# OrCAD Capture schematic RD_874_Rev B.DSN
size B; title: DER-874 rev B; rev: B
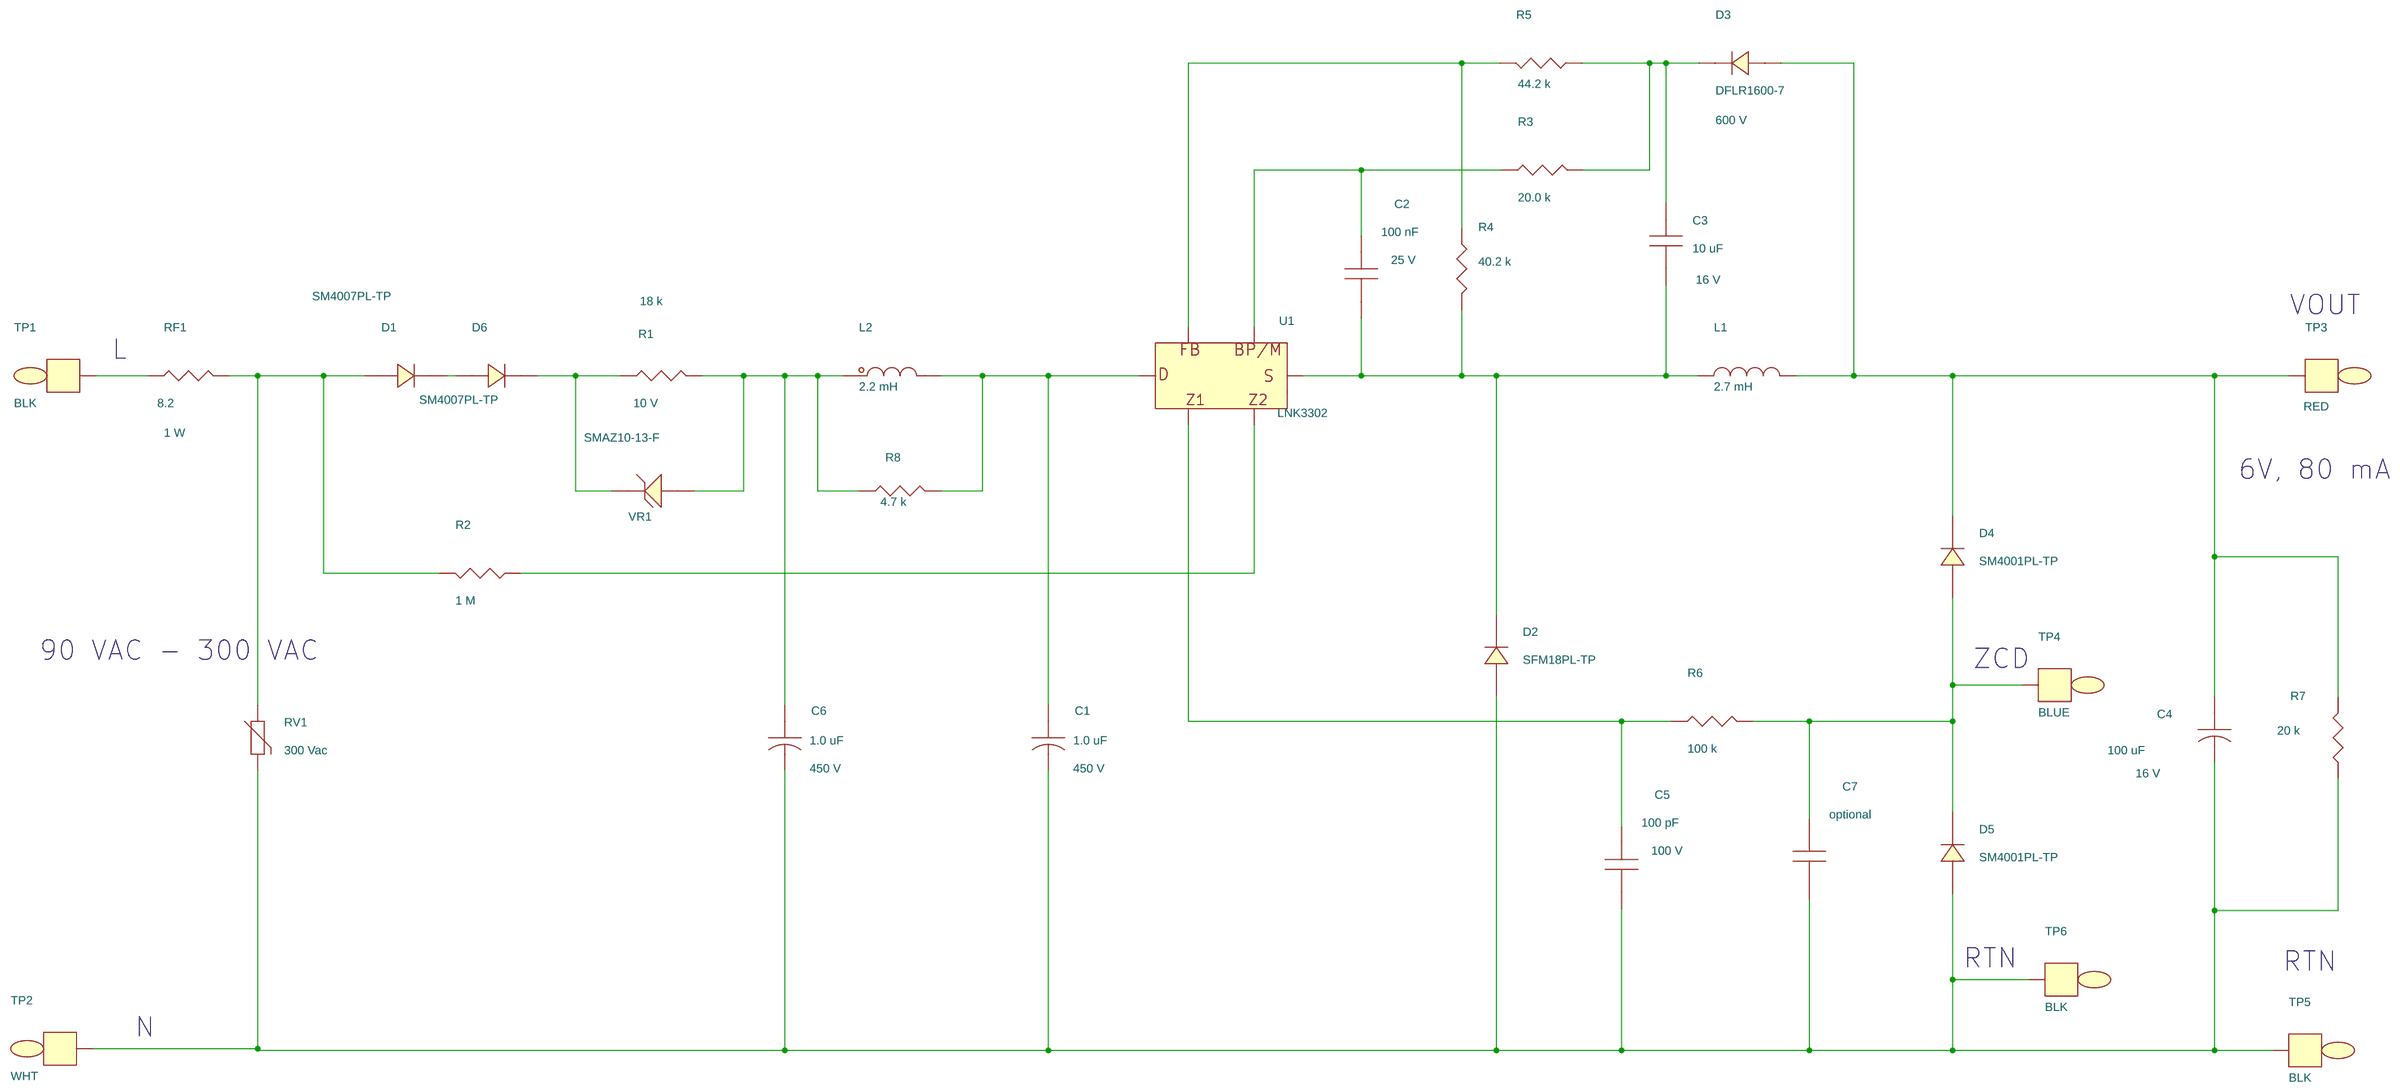
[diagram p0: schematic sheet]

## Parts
C1  1.0 uF  [pipolcapclyd320ls140030]
C2  100 nF  [pismc0805]
C3  10 uF  [pismc0805]
C4  100 uF  [pipolcapclyd248ls098028]
C5  100 pF  [pismc0805]
C6  1.0 uF  [pipolcapclyd320ls140030]
C7  optional  [pismc0805]
D1  SM4007PL-TP  [pi_sm_sod-123_12]
D2  SFM18PL-TP  [pi_sm_sod-123_12]
D3  DFLR1600-7  [pismddflr120012]
D4  SM4001PL-TP  [pi_sm_sod-123_12]
D5  SM4001PL-TP  [pi_sm_sod-123_12]
D6  SM4007PL-TP  [pi_sm_sod-123_12]
L1  2.7 mH  [pi_choke_vd8p0h7p5ls5p0d0p6]
L2  2.2 mH  [pi_choke_RL5480-1_d2]
R1  18 k  [pismr0805]
R2  1 M  [pismr0805]
R3  20.0 k  [pismr1206]
R4  40.2 k  [pismr0805]
R5  44.2 k  [pismr0805]
R6  100 k  [pismr0805]
R7  20 k  [pismr0805]
R8  4.7 k  [pismr0805]
RF1  8.2  [pi12wresd180ls575040]
RV1  300 Vac  [pi_disc276x181_ls200x83d040]
TP1  BLK  [pitpkeystone100x100]
TP2  WHT  [pitpkeystone100x100]
TP3  RED  [pitpkeystone100x100]
TP4  BLUE  [pitpkeystone100x100]
TP5  BLK  [pitpkeystone100x100]
TP6  BLK  [pitpkeystone100x100]
U1  LNK3302  [pismso8_nop3]
VR1  SMAZ10-13-F  [pismdo214ac12]

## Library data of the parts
C1 C6 = CAP_POL: ALT_SYMBOLS: pipolcapclyd320ls140030h; Disp_Voltage: 450 V; FPLIST: pipolcapclyd320ls140030,pipolcapclyd320ls140030430h,pipolcapclyd320ls140030h; Part Number: 20-00955-00; Voltage: 450 V
C2 = CAP_NP: Disp_Voltage: 25 V; Part Number: 20-08599-00; Voltage: 25 V
C3 = CAP_NP: Disp_Voltage: 16 V; Part Number: 20-08964-00; Voltage: 16 V
C4 = CAP_POL: ALT_SYMBOLS: pipolcapclyd248ls098028_h; Disp_Voltage: 16 V; FPLIST: pipolcapclyd248ls098028,pipolcapclyd248ls098028_h; Part Number: 20-09114-00; Voltage: 16V
C5 C7 = CAP_NP: Disp_Voltage: 100 V; Part Number: 20-00581-00; Voltage: 100 V
D1 D6 = DIODE: Part Number: 15-01070-00
D2 = DIODE: Part Number: 15-01634-00
D3 = DIODE: Disp_Voltage: 600 V; Part Number: 15-00826-00
D4 D5 = DIODE: Part Number: 15-01598-00; ROOM: 2
L1 = INDUCTOR: Part Number: 30-00435-00
L2 = INDUCTOR_DOT2: Part Number: 30-00272-00
R1 = R: Part Number: 05-01549-00
R2 = R: Part Number: 05-01591-00; ROOM: 1
R3 = R: Disp_Tol: 1%; Part Number: 05-00318-00
R4 = R: Disp_Tol: 1%; Part Number: 05-00742-00; Tol: 1%
R5 = R: Disp_Tol: 1%; Part Number: 05-00746-00
R6 = R: Part Number: 05-01567-00; ROOM: 1
R7 = R: Part Number: 05-01550-00; Tol: 1%
R8 = R: Part Number: 05-01535-00; ROOM: 1
RF1 = RF: ALT_SYMBOLS: pi1wvresd120ls200d040; Disp_Power: 1 W; FPLIST: pi12wresd180ls575040,pi1wvresd120ls200d040; Part Number: 05-06353-00
RV1 = VARISTOR: Part Number: 85-00037-00
TP1 TP5 TP6 = TESTPOINT: Part Number: 35-00079-00
TP2 = TESTPOINT: Part Number: 35-00081-00
TP3 = TESTPOINT: Part Number: 35-00080-00; ROOM: 2
TP4 = TESTPOINT: Part Number: 35-00397-00
U1 = LNK-TNZ: Part Number: 10-01234-00
VR1 = DIODE_ZENER: Disp_Voltage: 10 V; Part Number: 15-01323-00

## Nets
N361382: D6.1 R1.2 VR1.1
N361822: C1.2 C4.2 C5.2 C6.2 C7.2 D2.2 D5.2 R7.2 RV1.2 TP2.1 TP5.1 TP6.1
N595771: D1.2 R2.2 RF1.2 RV1.1
N596154: RF1.1 TP1.1
N596955: C2.1 R3.1 U1.7
N596963: C3.1 D3.1 R3.2 R5.1
N597007: R4.1 R5.2 U1.8
N597039: C4.1 D3.2 D4.1 L1.2 R7.1 TP3.1
N597117: C2.2 C3.2 D2.1 L1.1 R4.2 U1.5
N597183: C1.1 L2.1 R8.2 U1.4
N597938: C6.1 L2.2 R1.1 R8.1 VR1.2
N605807: R2.1 U1.2
N607999: C7.1 D4.2 D5.1 R6.2 TP4.1
N609815: C5.1 R6.1 U1.1
N615244: D1.1 D6.2

Not connected (* = marked no-connect by the designer): U1 6

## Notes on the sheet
- VOUT
- L
- 6V, 80 mA
- 90 VAC - 300 VAC
- ZCD
- RTN
- RTN
- N
